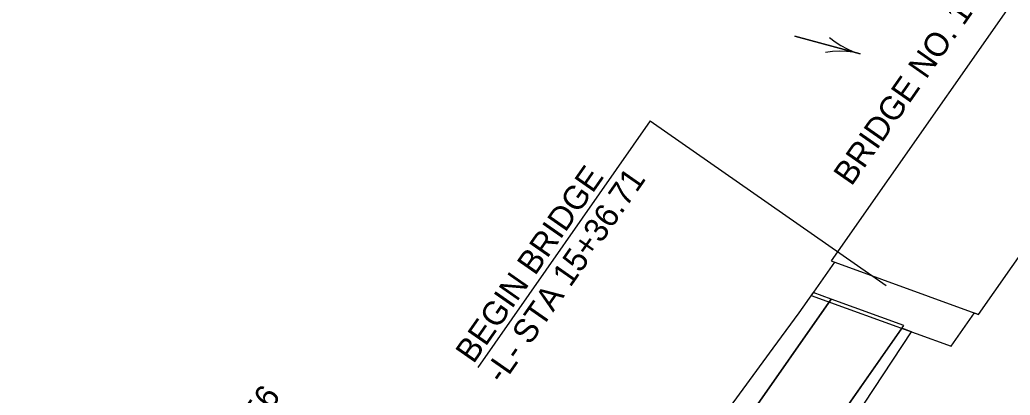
# Model space of a CAD drawing. Extents: x 1731327 to 1735374, y 884856 to 889832.
# Drawn here: x 1731930.3 to 1732222.4, y 885487.7 to 885598.5 of the extents above; entities that cross this region are included whole.
import ezdxf

# ---------------------------------------------------------------- set-up
doc = ezdxf.new("R2010")
doc.units = 0
for name, color, linetype in [('COGO Default Chain', 7, 'Continuous'), ('Exist Horizontal Baseline Alignment', 7, 'Continuous'), ('Exist Other Culture Area Outline', 7, 'Continuous'), ('Exist Roads EOP', 7, 'Continuous'), ('Exist Structure Minor Pipes RCP 24 Inch', 7, 'Continuous')]:
    doc.layers.add(name, color=color, linetype=linetype)

# ---------------------------------------------------------------- blocks, each defined once
blk = doc.blocks.new('EXIST HYDRO RIVER FLOW ARROW')
at = {"layer": 'COGO Default Chain'}
blk.add_line((0, 0), (0, 0), dxfattribs=at)
blk.add_lwpolyline([(0, 0.04575), (0.03775, 0.03), (0.07725, 0.01725), (0.118, 0.00775), (0.159, 0.0015), (0.2, 0), (-0.2, 0), (0.2, 0), (0.159, -0.0015), (0.118, -0.00775), (0.07725, -0.01725), (0.03775, -0.03), (0, -0.04575)], dxfattribs=at)

msp = doc.modelspace()

# ---------------------------------------------------------------- linework, layer by layer
at = {"layer": 'Exist Other Culture Area Outline'}
for q in [(1732065.36, 885495.8), (1732185.87, 885520.07)]:
    msp.add_line((1732116.22, 885568.68), q, dxfattribs=at)
at = {"layer": 'Exist Structure Minor Pipes RCP 24 Inch'}
for p, q in [((1732169.58, 885527.32), (1732213.12, 885511.49)), ((1732169.62, 885516.04), (1732116.34, 885439.87)), ((1732116.34, 885439.87), (1732169.62, 885516.04)), ((1732164.27, 885517.98), (1732160.1, 885512.01)), ((1732169.62, 885516.04), (1732164.27, 885517.98)), ((1732191.03, 885508.26), (1732169.62, 885516.04)), ((1732134.37, 885427.26), (1732191.03, 885508.26)), ((1732190.43, 885507.41), (1732134.37, 885427.26)), ((1732193.35, 885506.35), (1732190.43, 885507.41)), ((1732172.39, 885474.63), (1732193.35, 885506.34))]:
    msp.add_line(p, q, dxfattribs=at)
msp.add_lwpolyline([(1732163.68, 885517.13), (1732205.03, 885502.1), (1732211.91, 885511.93), (1732213.12, 885511.49), (1732281.91, 885609.82), (1732280.69, 885610.26), (1732287.56, 885620.08), (1732246.22, 885635.13), (1732239.34, 885625.29), (1732238.37, 885625.65), (1732169.58, 885527.32), (1732170.56, 885526.96)], close=True, dxfattribs=at)
for points in [[(1732160.1, 885512.01), (1732152.44, 885501.5), (1732125.88, 885465.23)], [(1732193.35, 885506.34), (1732193.35, 885506.35)]]:
    msp.add_lwpolyline(points, dxfattribs=at)

# ---------------------------------------------------------------- block references
at = {"layer": 'COGO Default Chain', "xscale": 49.99999999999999, "yscale": 50.00000000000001, "rotation": -15.06387940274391}
msp.add_blockref('EXIST HYDRO RIVER FLOW ARROW', (1732168.55, 885591.05), dxfattribs=at)

# ---------------------------------------------------------------- texts
at = {"layer": 'Exist Horizontal Baseline Alignment'}
msp.add_text('BEGIN TIP PROJECT B-4756', height=7, rotation=55.0251, dxfattribs=at).set_placement((1731935.56, 885384.66))
at = {"layer": 'Exist Roads EOP'}
for s, p in [('BRIDGE NO. 120', (1732175.6, 885549.12)), ('BEGIN BRIDGE', (1732064.09, 885496.69)), ('-L- STA 15+36.71', (1732072.7, 885490.68))]:
    msp.add_text(s, height=7, rotation=55.0911, dxfattribs=at).set_placement(p)

doc.saveas('drawing.dxf')
